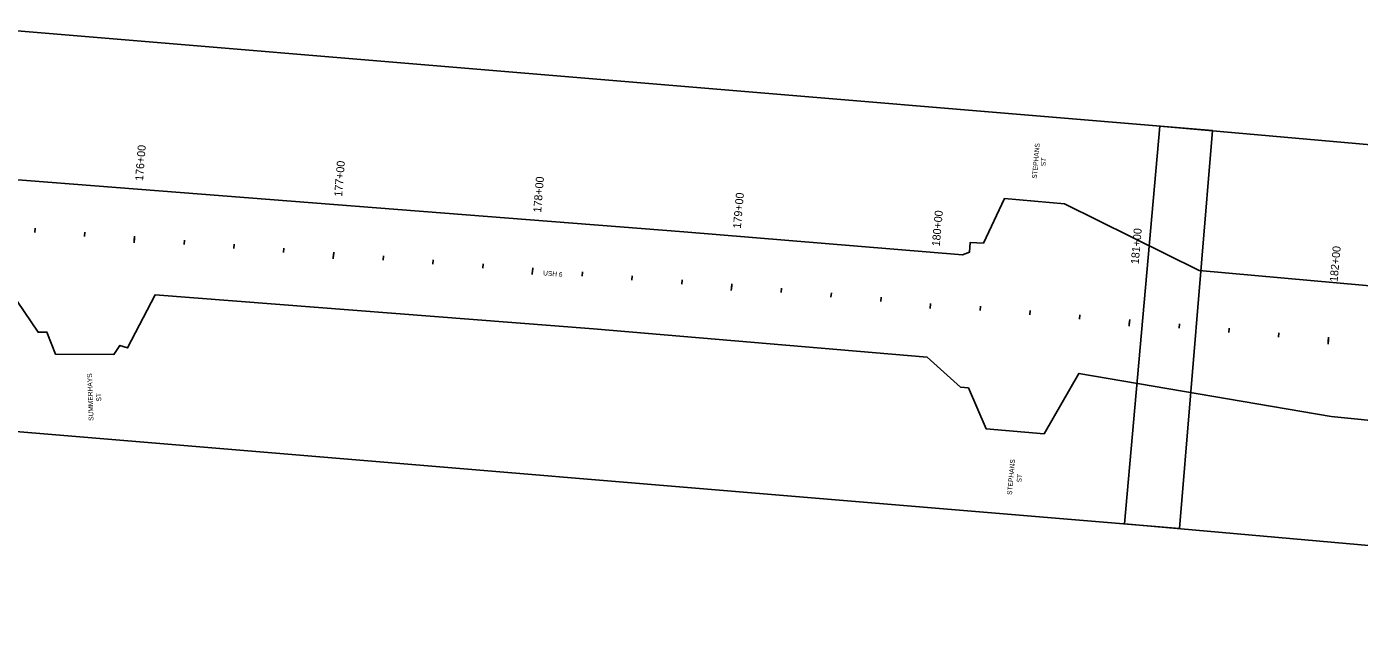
# Model space of a CAD drawing. Extents: x 20499876 to 20505320, y 7953544 to 7954108.
# Drawn here: x 20501256 to 20501924, y 7953735 to 7954040 of the extents above; entities that cross this region are included whole.
import ezdxf

# ---------------------------------------------------------------- set-up
doc = ezdxf.new("R2010")
doc.units = 0
for name, color, linetype in [('Alignment', 7, 'Continuous'), ('Curb', 7, 'Continuous'), ('Draft_0', 7, 'Continuous'), ('Draft_7', 7, 'Continuous'), ('UtilitiesBelowGround', 7, 'Continuous')]:
    doc.layers.add(name, color=color, linetype=linetype)

msp = doc.modelspace()

# ---------------------------------------------------------------- linework, layer by layer
at = {"layer": 'Alignment'}
for points in [[(20501225.23, 7954039.5), (20501208.63, 7953840.19), (20501833.46, 7953788.16), (20501850.06, 7953987.47)], [(20501823.68, 7953989.74), (20501806.03, 7953790.52), (20502430.58, 7953735.18), (20502448.23, 7953934.4)]]:
    msp.add_lwpolyline(points, close=True, dxfattribs=at)
at = {"layer": 'Curb'}
for p, q in [((20501310.13, 7953932.39), (20501310.3, 7953934.57)), ((20501409.81, 7953924.47), (20501409.99, 7953926.65)), ((20501509.5, 7953916.55), (20501509.67, 7953918.73)), ((20501609.18, 7953908.55), (20501609.37, 7953910.73)), ((20501708.89, 7953900.86), (20501708.67, 7953898.42)), ((20501808.38, 7953890.72), (20501808.58, 7953892.89)), ((20501907.98, 7953881.8), (20501908.18, 7953883.97))]:
    msp.add_line(p, q, dxfattribs=at)
at = {"layer": 'Draft_7'}
for p, q in [((20501260.29, 7953936.35), (20501260.46, 7953938.53)), ((20501285.21, 7953934.37), (20501285.38, 7953936.55)), ((20501310.23, 7953933.61), (20501310.03, 7953931.17)), ((20501335.05, 7953930.41), (20501335.22, 7953932.59)), ((20501359.97, 7953928.43), (20501360.14, 7953930.61)), ((20501384.89, 7953926.45), (20501385.07, 7953928.63)), ((20501409.91, 7953925.69), (20501409.72, 7953923.25)), ((20501434.74, 7953922.49), (20501434.91, 7953924.67)), ((20501459.66, 7953920.51), (20501459.83, 7953922.69)), ((20501484.58, 7953918.53), (20501484.75, 7953920.71)), ((20501509.6, 7953917.77), (20501509.4, 7953915.33)), ((20501534.42, 7953914.57), (20501534.59, 7953916.75)), ((20501559.34, 7953912.59), (20501559.52, 7953914.76)), ((20501584.26, 7953910.61), (20501584.44, 7953912.78)), ((20501609.29, 7953909.77), (20501609.07, 7953907.34)), ((20501634.08, 7953906.33), (20501634.28, 7953908.5)), ((20501658.98, 7953904.1), (20501659.18, 7953906.27)), ((20501683.88, 7953901.87), (20501684.08, 7953904.04)), ((20501708.89, 7953900.86), (20501708.67, 7953898.42)), ((20501733.68, 7953897.41), (20501733.88, 7953899.58)), ((20501758.58, 7953895.18), (20501758.78, 7953897.35)), ((20501783.48, 7953892.95), (20501783.68, 7953895.12)), ((20501808.49, 7953891.94), (20501808.27, 7953889.5)), ((20501833.28, 7953888.49), (20501833.48, 7953890.66)), ((20501858.18, 7953886.26), (20501858.38, 7953888.43)), ((20501883.08, 7953884.03), (20501883.28, 7953886.2)), ((20501908.09, 7953883.02), (20501907.88, 7953880.58))]:
    msp.add_line(p, q, dxfattribs=at)
at = {"layer": 'UtilitiesBelowGround'}
for points in [[(20500961.05, 7953985.49), (20501585.27, 7953936.81), (20501724.91, 7953925.27), (20501728.32, 7953926.51), (20501728.73, 7953931.44), (20501735.34, 7953931.05), (20501745.91, 7953953.5), (20501775.93, 7953950.79), (20501843.37, 7953917.33), (20502120.24, 7953892.49), (20502373.22, 7953872.83), (20502501.07, 7953863.11), (20502518.94, 7953887.24), (20502524.88, 7953886.71), (20502539.39, 7953890.66), (20502579.49, 7953887.98), (20502593.01, 7953888.5)], [(20502125.33, 7953822.5), (20501909.53, 7953844.31), (20501783.16, 7953865.85), (20501765.7, 7953835.6), (20501736.68, 7953838.13), (20501727.8, 7953858.68), (20501723.86, 7953859.03), (20501707.21, 7953873.97), (20501540.13, 7953888.22), (20501320.52, 7953905.16), (20501306.78, 7953878.61), (20501302.9, 7953879.88), (20501299.93, 7953875.35), (20501270.66, 7953875.56), (20501266.35, 7953886.51), (20501261.93, 7953886.46), (20501244.4, 7953912.4)]]:
    msp.add_lwpolyline(points, dxfattribs=at)

# ---------------------------------------------------------------- texts
at = {"layer": 'Curb'}
msp.add_text('180+00', height=4.008, rotation=84.88337, dxfattribs=at).set_placement((20501713.45, 7953929.34))
at = {"layer": 'Draft_0'}
for s, rotation, p in [('STEPHANS', 85, (20501762.02, 7953963.27)), ('ST', 85, (20501766.42, 7953969.49)), ('USH 6', 355, (20501514.75, 7953915)), ('SUMMERHAYS', 91.87706, (20501289.72, 7953842.13)), ('ST', 91.87706, (20501293.61, 7953851.81)), ('STEPHANS', 85, (20501749.6, 7953804.95)), ('ST', 85, (20501754.36, 7953811.14))]:
    msp.add_text(s, height=2.4, rotation=rotation, dxfattribs=at).set_placement(p)
at = {"layer": 'Draft_7'}
for s, rotation, p in [('176+00', 85.45642, (20501314.5, 7953962.14)), ('177+00', 85.45642, (20501414.19, 7953954.22)), ('178+00', 85.45642, (20501513.87, 7953946.3)), ('179+00', 84.88337, (20501613.85, 7953938.26)), ('180+00', 84.88337, (20501713.45, 7953929.34)), ('181+00', 84.88337, (20501813.05, 7953920.42)), ('182+00', 84.88337, (20501912.66, 7953911.5))]:
    msp.add_text(s, height=4.008, rotation=rotation, dxfattribs=at).set_placement(p)

doc.saveas('drawing.dxf')
